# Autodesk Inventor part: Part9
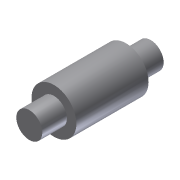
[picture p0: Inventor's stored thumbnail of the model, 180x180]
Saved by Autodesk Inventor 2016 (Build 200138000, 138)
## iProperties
Shininess: 77.0
Length Units: 11269
Angle Units: 11279
Time Units: 11290
Mass Units: 11283
Length Display Precision: 3
Angle Display Precision: 2
Created: 2002-01
Part Number: Part9
Document SubType Name: Modeling
Designer: ***
Density: 1 g/cm^3
Material: Generic
Appearance: Default
Density: 0.0
Volumn: 0.0
Area: 0.0
PropertySet Name: Model Information
Control State: 0
Master: False
Checked Out: False
Author: ***
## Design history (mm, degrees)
sketch "Sketch1"
  geometry: L1 (0.279, 23.245)-(5.19, 23.245); L2 (5.19, 23.245)-(5.19, 13.947); L3 (5.19, 13.947)-(8.761, 13.947); L4 (8.761, 13.947)-(8.761, -13.295); L5 (8.761, -13.295)-(5.19, -13.295); L6 (5.19, -13.295)-(5.19, -22.592); L7 (5.19, -22.592)-(0.279, -22.592); L8 (0.279, -22.592)-(0.279, 23.245)
  constraints: 16 end point, 5 parallel, 2 equal length, 1 collinear, 1 horizontal, 1 perpendicular
revolve "Revolution1" sketch "Sketch1" stored, may be unused: angle "d0" = 90 deg
body "Solid1"
